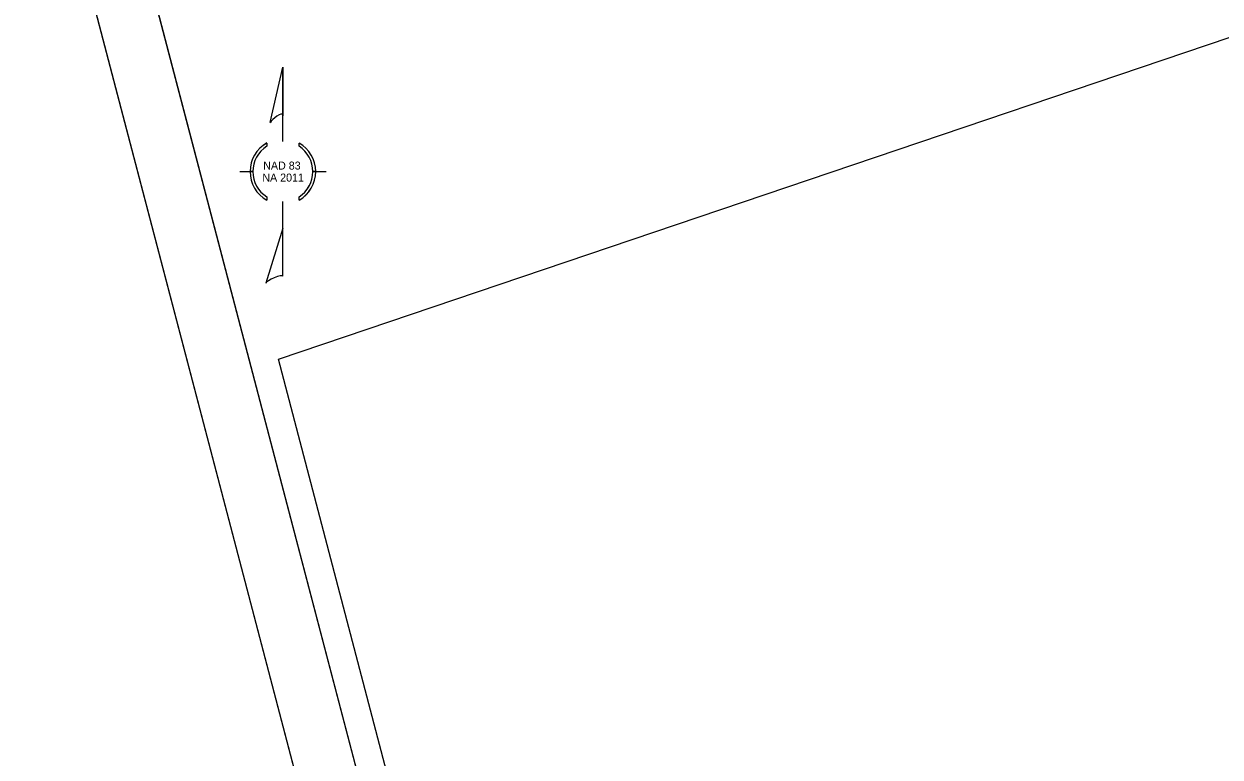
# Model space of a CAD drawing. Extents: x 1366711 to 1368206, y 878140 to 880064.
# Drawn here: x 1366711 to 1367458, y 879147 to 879606 of the extents above; entities that cross this region are included whole.
import ezdxf

# ---------------------------------------------------------------- set-up
doc = ezdxf.new("R2010")
doc.units = 0
for name, color, linetype in [('Exist Environmental Wetland Boundary Cogo Point CELL', 7, 'Continuous'), ('Exist Hydro Jurisdictional Stream or Body of Water Mitigable', 7, 'Continuous'), ('Exist Hydro Jurisdictional Stream or Body of Water Mitigable Cogo Number', 7, 'Continuous'), ('Exist Hydro Jurisdictional Stream or Body of Water NonMitigable', 7, 'Continuous'), ('Sheet_Data_Text_CELL', 7, 'Continuous'), ('Sheet_Plan_CELL', 7, 'Continuous')]:
    doc.layers.add(name, color=color, linetype=linetype)

msp = doc.modelspace()

# ---------------------------------------------------------------- linework, layer by layer
at = {"layer": 'Exist Environmental Wetland Boundary Cogo Point CELL'}
msp.add_lwpolyline([(1367149.56, 878329.29), (1366869.99, 879396.08), (1367795.92, 879709.62), (1368092.87, 878576.5)], close=True, dxfattribs=at)
at = {"layer": 'Exist Hydro Jurisdictional Stream or Body of Water Mitigable'}
for p, q in [((1366864.74, 879543.85), (1366872.61, 879578.62)), ((1366872.64, 879578.62), (1366872.61, 879578.62)), ((1366872.64, 879578.62), (1366872.61, 879578.62)), ((1366872.64, 879578.62), (1366872.65, 879548.15)), ((1366872.66, 879532.02), (1366872.64, 879578.62)), ((1366872.65, 879548.15), (1366872.65, 879549.01)), ((1366872.65, 879549.01), (1366872.67, 879549.01)), ((1366862.58, 879531.14), (1366862.58, 879531.12)), ((1366862.58, 879531.12), (1366862.58, 879529.08)), ((1366882.76, 879529.07), (1366882.76, 879531.12)), ((1366845.67, 879513.26), (1366853.92, 879513.27)), ((1366852.16, 879513.26), (1366853.92, 879513.27)), ((1366853.92, 879513.27), (1366852.17, 879513.26)), ((1366891.42, 879513.28), (1366899.67, 879513.28)), ((1366891.42, 879513.28), (1366893.17, 879513.28)), ((1366893.17, 879513.28), (1366891.42, 879513.28)), ((1366862.6, 879497.46), (1366862.6, 879495.41)), ((1366872.69, 879447.92), (1366872.67, 879494.52)), ((1366882.78, 879495.44), (1366882.77, 879497.48)), ((1366882.78, 879495.42), (1366882.78, 879495.44)), ((1366872.66, 879477.92), (1366861.92, 879443.45)), ((1366872.7, 879447.92), (1366872.66, 879477.92))]:
    msp.add_line(p, q, dxfattribs=at)
for radius, start, end in [(20.5, 119.4572, 240.58888), (20.5, 299.54346, 60.50262), (20.5, 0.02304, 60.50262), (18.75, 122.5262, 237.51987), (18.75, 302.62361, 57.42246), (18.75, 0.02304, 57.42246), (20.5, 180.02304, 240.58888), (18.75, 180.02304, 237.51987)]:
    msp.add_arc((1366872.67, 879513.27), radius, start, end, dxfattribs=at)
for centre, major_axis, ratio, start_param, end_param in [((1366868.63, 879546.01), (3.99, 3.06), 0.261723, 6.225794, 8.917625), ((1366872.67, 879513.27), (-0.01, 20.53), 0.998737, 0.514018, 1.570796), ((1366872.67, 879513.27), (-0.01, 18.77), 0.998737, 0.567287, 1.570796), ((1366872.67, 879513.27), (-0.01, 18.77), 0.998737, 3.71058, 4.712389), ((1366872.67, 879513.27), (-0.01, 20.53), 0.998737, 3.657116, 4.712389), ((1366867.31, 879445.5), (5.38, 2.43), 0.225493, 6.280036, 9.220301)]:
    msp.add_ellipse(centre, major_axis=major_axis, ratio=ratio, start_param=start_param, end_param=end_param, dxfattribs=at)
at = {"layer": 'Exist Hydro Jurisdictional Stream or Body of Water Mitigable Cogo Number'}
msp.add_line((1366756.62, 879758.15), (1367168.57, 878186.24), dxfattribs=at)
at = {"layer": 'Exist Hydro Jurisdictional Stream or Body of Water NonMitigable'}
msp.add_line((1367141.8, 878140.46), (1366710.84, 879784.92), dxfattribs=at)
at = {"layer": 'Sheet_Data_Text_CELL'}
msp.add_lwpolyline([(1367141.8, 878140.46), (1366710.84, 879784.92), (1367774.9, 880063.78), (1368205.86, 878419.32)], close=True, dxfattribs=at)
at = {"layer": 'Sheet_Plan_CELL'}
msp.add_lwpolyline([(1367168.57, 878186.24), (1366781.97, 879661.42), (1367773.49, 879921.26), (1368160.08, 878446.08)], close=True, dxfattribs=at)

# ---------------------------------------------------------------- texts
at = {"layer": 'Exist Hydro Jurisdictional Stream or Body of Water Mitigable'}
for s, p in [('NAD 83', (1366860.36, 879514.52)), ('NA 2011', (1366859.82, 879507.02))]:
    msp.add_text(s, height=5, rotation=0.02304, dxfattribs=at).set_placement(p)

doc.saveas('drawing.dxf')
